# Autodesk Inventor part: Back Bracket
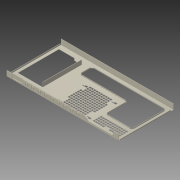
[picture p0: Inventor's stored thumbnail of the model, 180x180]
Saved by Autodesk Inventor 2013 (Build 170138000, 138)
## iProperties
Created: 2007-02
Material: Allgemein
Document SubType Name: Sheet Metal
Mass: 49.0206 g
Surface Area: 1055.08 cm^2
Volume: 49.0206 cm^3
Density: 1 g/cm^3
Flat Pattern Width: 37.4953 cm
Flat Pattern Length: 21.3621 cm
Flat Pattern Area: 800.978 cm^2
Sheet Metal Rule: 1 mm
Sheet Metal Width: 374.953 mm
Sheet Metal Length: 213.621 mm
Sheet Metal Area: 80097.779 mm^2
Area: =<FLAT PATTERN AREA> cm^2
Length: =<FLAT PATTERN LENGTH> cm
Width: =<FLAT PATTERN WIDTH> cm
Author: Autodesk, Inc.
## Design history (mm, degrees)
node "Face1"
node "Flange1"
node "Flange2"
node "Flange3"
feature "Corner4" dims "d32" = 4 (= CornerReliefSize), "d33" = 0.5 (= BendRadius), "d34" = 0.5 (= 0.5 x Thickness), "d35" = 0, "Thickness" = 1
feature "Corner5" dims "d36" = 4 (= CornerReliefSize), "d37" = 0.5 (= BendRadius), "d38" = 0.5 (= 0.5 x Thickness), "d39" = 0, "Thickness" = 1
feature "Corner6" dims "d40" = 4 (= CornerReliefSize), "d41" = 0.5 (= BendRadius), "d42" = 0.5 (= 0.5 x Thickness), "d43" = 0, "Thickness" = 1
cut "Cut1" dims "d47" = 1 (= Thickness), "d48" = 0
node "Flange4"
cut "Cut2" dims "d63" = 1 (= Thickness), "d64" = 0
feature "iFeature1:1" dims "d74" = 10 (= d75), "d75" = 10, "d76" = 8, "d77" = 1 (= d78), "d78" = 1, "d79" = 1.5, "d80" = 0.5, "d81" = 1, "d82" = 5 (= 0.5 x d75), "d83" = 4 (= 0.5 x d76)
feature "Corner Round1" dims "d85" = 10, "d86" = 5, "d87" = 2
feature "Hem1" dims "d88" = 1 (= BendReliefWidth), "d89" = 0.5 (= BendReliefDepth), "d90" = 2 (= MinimumRemnant), "d91" = 0.5 (= BendRadius), "d92" = 3 (= 3 x Thickness), "d93" = 0.5 (= 0.5 x Thickness), "d94" = 0.25 (= 0.5 x d93), "SeamGap" = 0.01, "Thickness" = 1
feature "Hem2" dims "d95" = 1 (= BendReliefWidth), "d96" = 0.5 (= BendReliefDepth), "d97" = 2 (= MinimumRemnant), "d98" = 0.5 (= BendRadius), "d99" = 3 (= 3 x Thickness), "d100" = 0.5 (= 0.5 x Thickness), "d101" = 0.25 (= 0.5 x d100), "SeamGap" = 0.01, "Thickness" = 1
feature "Hem3" dims "d102" = 1 (= BendReliefWidth), "d103" = 0.5 (= BendReliefDepth), "d104" = 2 (= MinimumRemnant), "d105" = 0.5 (= BendRadius), "d106" = 3 (= 3 x Thickness), "d107" = 0.5 (= 0.5 x Thickness), "d108" = 0.25 (= 0.5 x d107), "SeamGap" = 0.01, "Thickness" = 1
cut "Cut3" dims "d116" = 1 (= Thickness), "d117" = 0
node "Flange5"
cut "Cut4" dims "d146" = 1 (= Thickness), "d147" = 0
feature "Corner Round2" dims "d148" = 5
node "Flange6"
feature "iFeature2:1" dims "d167" = 6, "d168" = 8.2, "d169" = 2.5, "d170" = 15
feature "iFeature2:2" dims "d181" = 6, "d182" = 8.2, "d183" = 2.5, "d184" = 15
feature "iFeature3:1" dims "d196" = 6, "d197" = 6 (= d196)
feature "iFeature3:2" dims "d210" = 6, "d211" = 6 (= d210)
feature "iFeature4:1" dims "d218" = 11.8, "d219" = 1.4
body "Solid1"
sketch "Sketch1"
  geometry: L1 (-89, 184)-(89, 184); L2 (89, 184)-(89, -184); L3 (89, -184)-(-89, -184); L4 (-89, -184)-(-89, 184); L5 (-89, 184)-(89, -184); 2 further points
  constraints: 10 end point, 2 parallel, 1 coincident, 1 horizontal, 1 midpoint, 1 perpendicular
  dimensions: "d0" = 368 distance of L3.end L1.start; "d1" = 178 distance of L2.end L3.end
face "Plate1" dims "Thickness" = 1
sketch "Sketch2"
  geometry: L1 through (-184, 0) direction (1, 0); L2 through (0, 9) direction (0, 1); L3 (0, 18)-(-368, 18); L4 (-368, 18)-(-368, 0)
  constraints: 6 end point, 1 horizontal, 1 perpendicular, 1 vertical
face "Plate2" dims "d3" = 1 (= BendReliefWidth), "d4" = 0.5 (= BendReliefDepth), "d5" = 2 (= MinimumRemnant), "d6" = 0.5 (= BendRadius), "d7" = 18, "d8" = 90 deg, "d9" = 0.5 (= BendRadius), "d10" = 4 (= CornerReliefSize), "d11" = 1 (= Thickness), "d221" = 1 (= JacobiRadiusSize), "SeamGap" = 0.01, "Thickness" = 1
bend "Bend1" dims "d3" = 1 (= BendReliefWidth), "d4" = 0.5 (= BendReliefDepth), "d5" = 2 (= MinimumRemnant), "d6" = 0.5 (= BendRadius), "d7" = 18, "d8" = 90 deg, "d9" = 0.5 (= BendRadius), "SeamGap" = 0.01, "Thickness" = 1
feature "Corner1" dims "d7" = 18, "d8" = 90 deg, "d10" = 4 (= CornerReliefSize), "d11" = 1 (= Thickness), "d221" = 1 (= JacobiRadiusSize)
sketch "Sketch3"
  geometry: L1 through (-87.5, 0) direction (1, 0); L2 through (0, 2.5) direction (0, 1); L3 (0, 5)-(-175, 5); L4 (-175, 5)-(-175, 0)
  constraints: 6 end point, 1 horizontal, 1 perpendicular, 1 vertical
face "Plate3" dims "d12" = 1 (= BendReliefWidth), "d13" = 0.5 (= BendReliefDepth), "d14" = 2 (= MinimumRemnant), "d15" = 0.5 (= BendRadius), "d16" = 5, "d17" = 90 deg, "d18" = 0.5 (= BendRadius), "d19" = 4 (= CornerReliefSize), "d20" = 1 (= Thickness), "d222" = 1 (= JacobiRadiusSize), "SeamGap" = 0.01, "Thickness" = 1
bend "Bend2" dims "d12" = 1 (= BendReliefWidth), "d13" = 0.5 (= BendReliefDepth), "d14" = 2 (= MinimumRemnant), "d15" = 0.5 (= BendRadius), "d16" = 5, "d17" = 90 deg, "d18" = 0.5 (= BendRadius), "SeamGap" = 0.01, "Thickness" = 1
feature "Corner2" dims "d16" = 5, "d17" = 90 deg, "d19" = 4 (= CornerReliefSize), "d20" = 1 (= Thickness), "d222" = 1 (= JacobiRadiusSize)
sketch "Sketch4"
  geometry: L1 (-8.5, 0)-(-175, 0); L2 (-175, 0)-(-175, 5); L3 (-175, 5)-(-8.5, 5); L4 (-8.5, 5)-(-8.5, 0)
  constraints: 8 end point
face "Plate4" dims "d21" = 1 (= BendReliefWidth), "d22" = 0.5 (= BendReliefDepth), "d23" = 2 (= MinimumRemnant), "d24" = 0.5 (= BendRadius), "d25" = 8.5, "d26" = 0, "d27" = 5, "d28" = 90 deg, "d29" = 0.5 (= BendRadius), "d30" = 4 (= CornerReliefSize), "d31" = 1 (= Thickness), "d223" = 1 (= JacobiRadiusSize), "SeamGap" = 0.01, "Thickness" = 1
bend "Bend3" dims "d21" = 1 (= BendReliefWidth), "d22" = 0.5 (= BendReliefDepth), "d23" = 2 (= MinimumRemnant), "d24" = 0.5 (= BendRadius), "d27" = 5, "d28" = 90 deg, "d29" = 0.5 (= BendRadius), "SeamGap" = 0.01, "Thickness" = 1
feature "Corner3" dims "d27" = 5, "d28" = 90 deg, "d30" = 4 (= CornerReliefSize), "d31" = 1 (= Thickness), "d223" = 1 (= JacobiRadiusSize)
sketch "Sketch5"
  geometry: L1 (4.5, 345.293)-(16.5, 345.293); L2 (16.5, 345.293)-(16.5, 315.293); L3 (16.5, 315.293)-(4.5, 315.293); L4 (4.5, 315.293)-(4.5, 345.293); L5 (16.5, 365.293)-(0, 365.293) reference; L6 (16.5, 365.293)-(16.5, 0) reference
  constraints: 8 end point, 2 parallel, 1 collinear, 1 horizontal, 1 perpendicular
  dimensions: "d44" = 30 distance of L1.end L2.end; "d45" = 12 distance of L2.end L3.end; "d46" = 20 distance between parallel lines of L1 L5
sketch "Sketch6"
  geometry: L1 (29, 0)-(1, 0); L2 (1, 0)-(1, 12); L3 (1, 12)-(29, 12); L4 (29, 12)-(29, 0)
  constraints: 8 end point
face "Plate5" dims "d49" = 1 (= BendReliefWidth), "d50" = 0.5 (= BendReliefDepth), "d51" = 2 (= MinimumRemnant), "d52" = 0.5 (= BendRadius), "d53" = 12, "d54" = 0, "d55" = 0.5 (= BendRadius), "d56" = 4 (= CornerReliefSize), "d57" = 1 (= Thickness), "d224" = 1 (= JacobiRadiusSize), "SeamGap" = 0.01, "Thickness" = 1
bend "Bend4" dims "d49" = 1 (= BendReliefWidth), "d50" = 0.5 (= BendReliefDepth), "d51" = 2 (= MinimumRemnant), "d52" = 0.5 (= BendRadius), "d53" = 12, "d54" = 0, "d55" = 0.5 (= BendRadius), "SeamGap" = 0.01, "Thickness" = 1
feature "Corner7" dims "d53" = 12, "d54" = 0, "d56" = 4 (= CornerReliefSize), "d57" = 1 (= Thickness), "d224" = 1 (= JacobiRadiusSize)
sketch "Sketch7"
  geometry: L1 (16.5, 18.646)-(6.5, 18.646); L2 (6.5, 18.646)-(6.5, 101.326); L3 (6.5, 101.326)-(16.5, 118.646); L4 (16.5, 118.646)-(16.5, 18.646); L5 (0, -1.354)-(3.5, -1.354) reference; L6 (16.5, 315.293)-(16.5, 0) reference
  constraints: 8 end point, 1 collinear, 1 horizontal, 1 parallel, 1 perpendicular
  dimensions: "d59" = 20 distance between parallel lines of L5 L1; "d60" = 10 distance of L1.start L1.end; "d61" = 100 distance from line of L3.end L1; "d62" = 150 deg angle of L3 L2
sketch "Sketch8" dims "d72" = 10
  geometry: L1 (16.5, 315.293)-(2.768, 315.293) reference; L2 (16.5, 315.293)-(16.5, 118.646) reference; 9 further points
  constraints: 1 vertical, 8 other
  dimensions: "d65" = 14 distance from line of point (8.5, 301.293) L1; "d66" = 8 distance from line of point (8.5, 301.293) L2; "d69" = 21 distance of point (8.5, 301.293) point (8.5, 280.293)
sketch "Sketch9"
  geometry: L1 (1, 0)-(0, 0); L2 (-0.5, 0)-(-0.5, -1.75); L3 (-0.5, -1.75)-(-1.5, -1.75); L4 (-1.5, -1.75)-(-1.5, 0); A1 r 0.25 centre (-0.25, 0) between (0, 0) and (-0.5, 0); A2 r 1.25 centre (-0.25, 0) between (1, 0) and (-1.5, 0)
  constraints: 8 end point, 4 point on circle
sketch "Sketch10"
  geometry: L1 (1, 0)-(0, 0); L2 (-0.5, 0)-(-0.5, -1.75); L3 (-0.5, -1.75)-(-1.5, -1.75); L4 (-1.5, -1.75)-(-1.5, 0); A1 r 0.25 centre (-0.25, 0) between (0, 0) and (-0.5, 0); A2 r 1.25 centre (-0.25, 0) between (1, 0) and (-1.5, 0)
  constraints: 8 end point, 4 point on circle
sketch "Sketch11"
  geometry: L1 (1, 0)-(0, 0); L2 (-0.5, 0)-(-0.5, -1.75); L3 (-0.5, -1.75)-(-1.5, -1.75); L4 (-1.5, -1.75)-(-1.5, 0); A1 r 0.25 centre (-0.25, 0) between (0, 0) and (-0.5, 0); A2 r 1.25 centre (-0.25, 0) between (1, 0) and (-1.5, 0)
  constraints: 8 end point, 4 point on circle
sketch "Sketch12"
  geometry: L1 (-73, 174)-(61, 174); L2 (61, 174)-(61, 94); L3 (61, 94)-(-66, 94); L4 (-66, 94)-(-66, 117); L5 (-66, 117)-(-73, 124); L6 (-73, 124)-(-73, 174); L7 (-89, -184)-(-89, 182.646) reference; L8 (87.646, 184)-(-87.646, 184) reference
  constraints: 12 end point, 3 parallel, 1 horizontal, 1 perpendicular
  dimensions: "d109" = 134 distance of L1.start L1.end; "d110" = 16 distance between parallel lines of L7 L6; "d111" = 23 distance of L3.end L4.end; "d112" = 135 deg angle of L5 L4; "d113" = 127 distance of L2.end L3.end; "d114" = 80 distance of L1.end L2.end; "d115" = 10 distance between parallel lines of L8 L1
sketch "Sketch13"
  geometry: L1 (-126.99, 0)-(-0.01, 0); L2 (-0.01, 0)-(-0.01, 15); L3 (-0.01, 15)-(-126.99, 15); L4 (-126.99, 15)-(-126.99, 0)
  constraints: 8 end point
face "Plate6" dims "d118" = 1 (= BendReliefWidth), "d119" = 0.5 (= BendReliefDepth), "d120" = 2 (= MinimumRemnant), "d121" = 0.5 (= BendRadius), "d122" = 15, "d123" = 90 deg, "d124" = 0.5 (= BendRadius), "d125" = 4 (= CornerReliefSize), "d126" = 1 (= Thickness), "d225" = 1 (= JacobiRadiusSize), "SeamGap" = 0.01, "Thickness" = 1
bend "Bend5" dims "d118" = 1 (= BendReliefWidth), "d119" = 0.5 (= BendReliefDepth), "d120" = 2 (= MinimumRemnant), "d121" = 0.5 (= BendRadius), "d122" = 15, "d123" = 90 deg, "d124" = 0.5 (= BendRadius), "SeamGap" = 0.01, "Thickness" = 1
feature "Corner8" dims "d122" = 15, "d123" = 90 deg, "d125" = 4 (= CornerReliefSize), "d126" = 1 (= Thickness), "d225" = 1 (= JacobiRadiusSize)
sketch "Sketch15"
  geometry: L1 (-75, 68)-(-75, -172); L2 (-75, -172)-(35.5, -172); L3 (35.5, -172)-(35.5, -87); L4 (35.5, -87)-(-35, -87); L5 (-35, -87)-(-35, 68); L6 (-35, 68)-(-75, 68); L7 (-89, -184)-(-89, 182.646) reference; L8 (-79, -184)-(87.646, -184) reference
  constraints: 12 end point, 4 parallel, 1 perpendicular, 1 vertical
  dimensions: "d140" = 240 distance of L1.start L1.end; "d141" = 40 distance of L5.end L1.start; "d142" = 14 distance between parallel lines of L7 L1; "d143" = 110.5 distance of L1.end L2.end; "d144" = 85 distance of L2.end L3.end; "d145" = 12 distance between parallel lines of L8 L2
sketch "Sketch16"
  geometry: L1 through (-72.5, 0) direction (1, -9.07e-34); L2 through (0, 2) direction (0, 1); L3 (0, 4)-(-145, 4); L4 (-145, 4)-(-145, 0)
  constraints: 6 end point, 1 horizontal, 1 perpendicular, 1 vertical
face "Plate7" dims "d149" = 1 (= BendReliefWidth), "d150" = 0.5 (= BendReliefDepth), "d151" = 2 (= MinimumRemnant), "d152" = 0.5 (= BendRadius), "d153" = 4, "d154" = 90 deg, "d155" = 0.5 (= BendRadius), "d156" = 4 (= CornerReliefSize), "d157" = 1 (= Thickness), "d226" = 1 (= JacobiRadiusSize), "SeamGap" = 0.01, "Thickness" = 1
bend "Bend6" dims "d149" = 1 (= BendReliefWidth), "d150" = 0.5 (= BendReliefDepth), "d151" = 2 (= MinimumRemnant), "d152" = 0.5 (= BendRadius), "d153" = 4, "d154" = 90 deg, "d155" = 0.5 (= BendRadius), "SeamGap" = 0.01, "Thickness" = 1
feature "Corner9" dims "d153" = 4, "d154" = 90 deg, "d156" = 4 (= CornerReliefSize), "d157" = 1 (= Thickness), "d226" = 1 (= JacobiRadiusSize)
sketch "Sketch17" dims "d165" = 10
  geometry: L1 (89, 182.646)-(89, -182.646) reference; L2 (87.646, 184)-(-87.646, 184) reference; 2 further points
  constraints: 1 vertical, 1 other
  dimensions: "d158" = 101 distance from line of L1 point (-12, 27.3); "d159" = 156.7 distance from line of L2 point (-12, 27.3); "d162" = 95 distance of point (-12, 27.3) point (-12, -67.7)
sketch "Sketch18" dims "d179" = 10
  geometry: L1 (-89, -61.321)-(-89, 132.646) reference; L2 (87.646, 184)-(-87.646, 184) reference; 2 further points
  constraints: 1 vertical, 1 other
  dimensions: "d172" = 16.9 distance from line of L1 point (-72.1, 27.3); "d173" = 156.7 distance from line of L2 point (-72.1, 27.3); "d176" = 95 distance of point (-72.1, 27.3) point (-72.1, -67.7)
sketch "Sketch19"
  geometry: L1 (87.646, 184)-(-87.646, 184) reference; L2 (89, 182.646)-(89, -182.646) reference; 144 further points
  constraints: 1 horizontal, 1 vertical, 143 other
  dimensions: "d186" = 161.75 distance from line of L1 point (67.25, 22.25); "d187" = 21.75 distance from line of L2 point (67.25, 22.25); "d190" = 7.5 distance of point (67.25, 22.25) point (67.25, 14.75); "d193" = 7.5 distance of point (67.25, 22.25) point (59.75, 22.25)
sketch "Sketch20"
  geometry: L1 (-79, -184)-(87.646, -184) reference; L2 (89, 182.646)-(89, -182.646) reference; 48 further points
  constraints: 1 horizontal, 1 vertical, 47 other
  dimensions: "d200" = 15 distance from line of L1 point (72, -169); "d201" = 17 distance from line of point (72, -169) L2; "d204" = 7.5 distance of point (72, -169) point (72, -161.5); "d207" = 7.5 distance of point (72, -169) point (64.5, -169)
sketch "Sketch21"
  geometry: L1 (87.646, 184)-(-87.646, 184) reference; L2 (89, 182.646)-(89, -182.646) reference; L3 (85.5, 92.8)-(85.5, -124.5); 2 further points
  constraints: 2 end point, 1 coincident, 1 parallel, 1 point on line
  dimensions: "d214" = 91.2 distance from line of L1 L3.start; "d215" = 3.5 distance from line of L2 L3.start; "d216" = 85.4 distance of point (85.5, 7.4) L3.start; "d217" = 131.9 distance of point (85.5, -124.5) point (85.5, 7.4)
feature "Definition1" dims "d0" = 1 (derived)
other parameters: "BendRadius" = 0.5, "BendReliefWidth" = 1 (= Thickness), "BendReliefDepth" = 0.5 (= 0.5 x Thickness), "CornerReliefSize" = 4 (= 4 x Thickness), "MinimumRemnant" = 2 (= 2 x Thickness), "TransitionRadius" = 0.5 (= BendRadius), "JacobiRadiusSize" = 1 (= Thickness), "d2" = 0.5 (= BendRadius), "d84" = 0, "d171" = 0, "d185" = 0, "d199" = 0, "d213" = 0, "d220" = 0, "GapSize" = 1 (= Thickness), "BendRadius" = 0.5, "BendReliefDepth" = 0.5, "BendReliefWidth" = 1, "CornerReliefSize" = 4, "JacobiRadiusSize" = 1, "MinimumRemnant" = 2, "Thickness" = 1, "TransitionRadius" = 0.5, "GapSize" = 1
